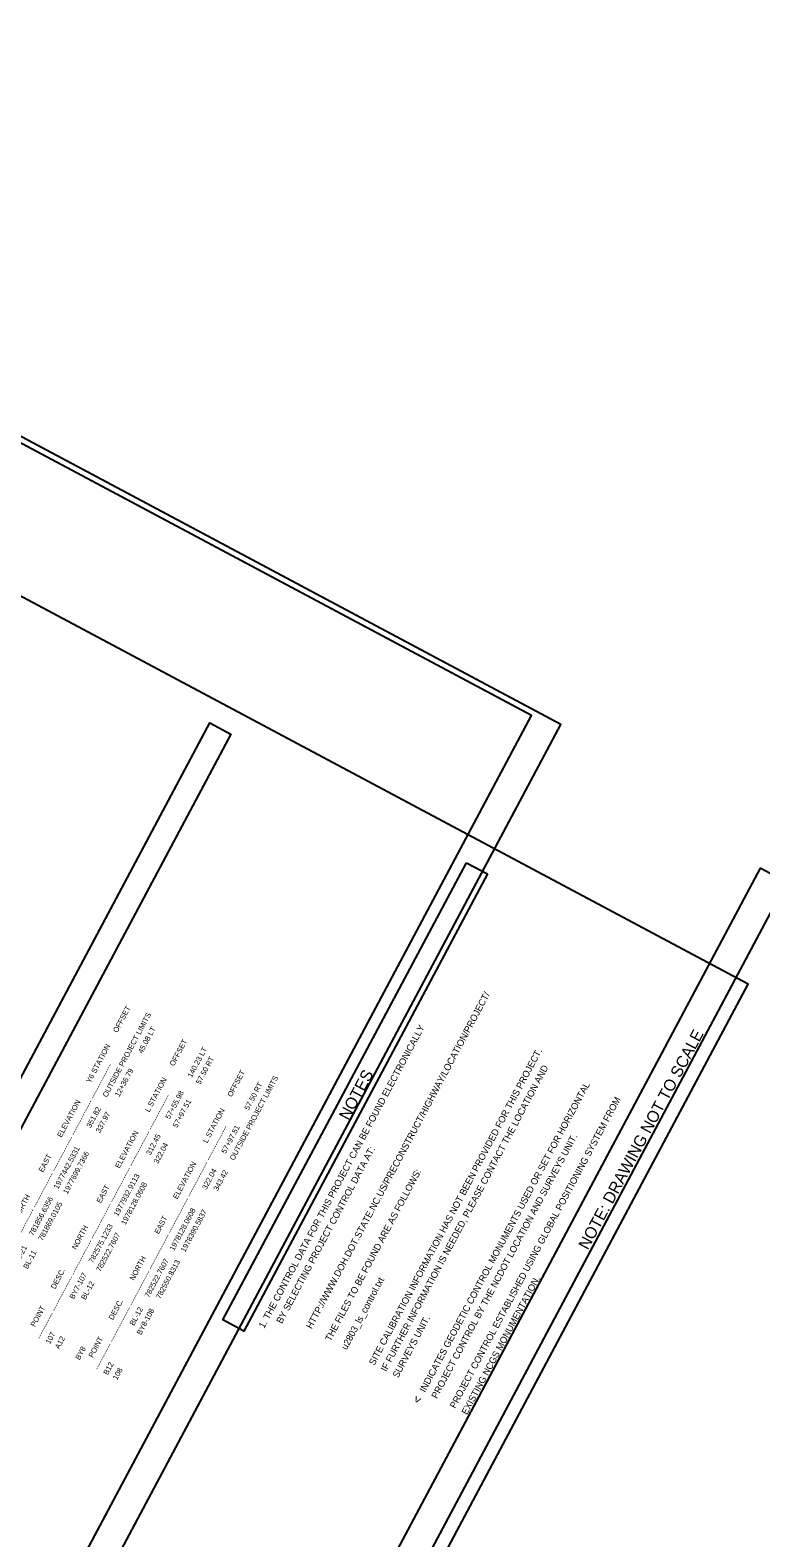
# Model space of a CAD drawing. Extents: x 1970823 to 1988115, y 770601 to 786368.
# Drawn here: x 1979025 to 1982294, y 779627 to 786368 of the extents above; entities that cross this region are included whole.
import ezdxf

# ---------------------------------------------------------------- set-up
doc = ezdxf.new("R2010")
doc.units = 0
for name, color, linetype in [('CTL Sheet Border CELL', 7, 'Continuous'), ('CTL Sheet Text', 7, 'Continuous'), ('Old_Level_2', 7, 'Continuous'), ('Old_Level_50', 7, 'Continuous'), ('Old_Level_51', 7, 'Continuous'), ('Old_Level_57', 7, 'Continuous'), ('Sheet Data Field CELL', 7, 'Continuous')]:
    doc.layers.add(name, color=color, linetype=linetype)

msp = doc.modelspace()

# ---------------------------------------------------------------- linework, layer by layer
at = {"layer": 'CTL Sheet Border CELL'}
for points in [[(1977401.8, 784679.3), (1973721.3, 777772.6), (1978555.9, 775196.3), (1982236.4, 782102.9)], [(1977121.9, 778191.4), (1979828.5, 783270.4), (1979922.1, 783220.5), (1977215.6, 778141.6)]]:
    msp.add_lwpolyline(points, close=True, dxfattribs=at)
for points in [[(1981070.6, 782595.7), (1979981.2, 780551.3), (1979887.5, 780601), (1980977, 782645.5)], [(1980977, 782645.5), (1981070.6, 782595.7)]]:
    msp.add_lwpolyline(points, dxfattribs=at)
at = {"layer": 'Old_Level_50'}
for points in [[(1975680.9, 786280.6), (1970978.5, 777456.3), (1976565.4, 774479.1), (1981267.8, 783303.4)], [(1982396.2, 782534.2), (1977693.8, 773709.9), (1983280.6, 770732.7), (1987983, 779557)]]:
    msp.add_lwpolyline(points, close=True, dxfattribs=at)
at = {"layer": 'Old_Level_51'}
for points in [[(1975574.8, 786367.7), (1970823, 777450.8), (1976647.6, 774346.9), (1981399.3, 783263.8)], [(1982290, 782621.4), (1977538.2, 773704.4), (1983362.8, 770600.5), (1988114.6, 779517.5)]]:
    msp.add_lwpolyline(points, close=True, dxfattribs=at)

# ---------------------------------------------------------------- texts
at = {"layer": 'CTL Sheet Text'}
for s, height, p in [('    POINT          DESC.           NORTH             EAST          ELEVATION          Y6 STATION       OFFSET', 23.75, (1978770.3, 780673.5)), ('21                     BY6-21      781856.6356     1977442.5331           351.82      OUTSIDE PROJECT LIMITS                 ', 23.75, (1978854.2, 780628.8)), ('A11                     BL-11      781869.0105     1977699.7366           337.97         12+36.79         45.08 LT', 23.75, (1978896.1, 780606.5)), ('    POINT          DESC.           NORTH             EAST          ELEVATION           L STATION       OFFSET', 23.75, (1979029.3, 780535.5)), ('107                   BY7-107      782575.1233     1977932.9113           312.45         57+55.98        140.23 LT', 23.75, (1979113.1, 780490.8)), ('------------ ---------------- ---------------- ---------------- ---------------- ---------------- ----------------', 23.75, (1978812.3, 780651.1)), ('A12                     BL-12      782522.7607     1978128.0608           322.04         57+97.51         57.50 RT', 23.75, (1979155, 780468.5)), ('NOTES', 52.17, (1980449.4, 781489.9)), ('    POINT          DESC.           NORTH             EAST          ELEVATION           L STATION       OFFSET', 23.75, (1979288.2, 780397.5)), ('B12                     BL-12      782522.7607     1978128.0608           322.04         57+97.51         57.50 RT', 23.75, (1979372.1, 780352.8)), ('108                   BY8-108      782550.8313     1978390.5837           343.42      OUTSIDE PROJECT LIMITS                 ', 23.75, (1979414, 780330.5)), ('------------ ---------------- ---------------- ---------------- ---------------- ---------------- ----------------', 23.75, (1979071.2, 780513.1)), ('------------ ---------------- ---------------- ---------------- ---------------- ---------------- ----------------', 23.75, (1979330.2, 780375.2)), ('BY8', 23.75, (1979246.3, 780419.8))]:
    msp.add_text(s, height=height, rotation=61.94709, dxfattribs=at).set_placement(p)
at = {"layer": 'Old_Level_2'}
for s, rotation, p in [('HTTP://WWW.DOH.DOT.STATE.NC.US/PRECONSTRUCT/HIGHWAY/LOCATION/PROJECT/', 61.94709, (1980284.2, 780558.4)), ('1. THE CONTROL DATA FOR THIS PROJECT CAN BE FOUND ELECTRONICALLY', 61.94709, (1980071.8, 780560.9)), ('SITE CALIBRATION INFORMATION HAS NOT BEEN PROVIDED FOR THIS PROJECT.', 61.94709, (1980565, 780395.5)), ('IF FURTHER INFORMATION IS NEEDED, PLEASE CONTACT THE LOCATION AND', 61.94709, (1980617.9, 780367.3)), ('INDICATES GEODETIC CONTROL MONUMENTS USED OR SET FOR HORIZONTAL', 61.84185, (1980791.5, 780274.7)), ('PROJECT CONTROL ESTABLISHED USING GLOBAL POSITIONING SYSTEM FROM', 61.84185, (1980926.4, 780202.8)), ('PROJECT CONTROL BY THE NCDOT LOCATION AND SURVEYS UNIT.', 61.84185, (1980844.4, 780246.4)), ('     BY SELECTING PROJECT CONTROL DATA AT:', 61.94709, (1980124.8, 780532.6)), ('THE FILES TO BE FOUND ARE AS FOLLOWS:', 61.94709, (1980369.2, 780502.9)), ('u2803_ls_control.txt', 61.94709, (1980440.9, 780464.7)), ('EXISTING NCGS MONUMENTATION.', 61.84185, (1980979.3, 780174.5)), ('SURVEYS UNIT.', 61.94709, (1980670.9, 780339.1))]:
    msp.add_text(s, height=30, rotation=rotation, dxfattribs=at).set_placement(p)
at = {"layer": 'Old_Level_57'}
msp.add_text('>', height=39.1, rotation=241.9613, dxfattribs=at).set_placement((1980747.8, 780266.5))
at = {"layer": 'Sheet Data Field CELL'}
msp.add_text('NOTE: DRAWING NOT TO SCALE', height=52.174, rotation=61.84185, dxfattribs=at).set_placement((1981520.1, 780910.8))

doc.saveas('drawing.dxf')
